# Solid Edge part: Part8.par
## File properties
Author: Deepak Maini
Template: Normal.par
Last saved by: MYPC
Revision: 38
Application: Solid Edge
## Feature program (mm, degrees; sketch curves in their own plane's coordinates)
sketch for "unnamed Protrusion 1" plane through (0, 0, 0) normal (0, 0, 1) x-axis (1, 0, 0)
  arc centre (32.4919, 0.608) radius 66.4976 from (-33.994, -0.6361) to (-18.3494, 43.4693) cw
  arc centre (0, 28) radius 24 from (-18.3494, 43.4693) to (18.3494, 43.4693) cw
  arc centre (-32.4919, 0.608) radius 66.4976 from (18.3494, 43.4693) to (33.994, -0.6361) cw
  arc centre (0, 0) radius 34 from (33.994, -0.6361) to (-33.994, -0.6361) cw
extrude "unnamed Protrusion 1" add finite 6 along -normal
sketch for "unnamed RevolvedProtrusion 1" plane through (0, 0, 0) normal (0, 0, 1) x-axis (1, 0, 0)
  line (0, 52) -> (0, -34)
  arc centre (0, 0) radius 34 from (0, -34) to (-33.994, -0.6361) cw
  arc centre (32.4919, 0.608) radius 66.4976 from (-33.994, -0.6361) to (-18.3494, 43.4693) cw
  arc centre (0, 28) radius 24 from (-18.3494, 43.4693) to (0, 52) cw
revolve "unnamed RevolvedProtrusion 1" add finite about sketch line (0, 51.9687) -> (0, 65.9821)
fillet "unnamed Round 1"
sketch for "unnamed Cutout 1" #1 plane through (0, 4, -6) normal (0, 0, -1) x-axis (-1, 0, 0)
  circle centre (13, -19) radius 2.5
sketch for "unnamed Cutout 1" #2 plane through (0, 4, -6) normal (0, 0, -1) x-axis (-1, 0, 0)
  circle centre (-13, -19) radius 2.5
  dimension (linear) = 13
extrude "unnamed Cutout 1" cut finite 3 along -normal
thinwall "unnamed Thinwall 1"
sketch for "unnamed Cutout 2" plane through (0, 0, 0) normal (0, 0, 1) x-axis (1, 0, 0)
  circle centre (0, 11) radius 8
extrude "unnamed Cutout 2" cut through along -normal
chamfer "unnamed Chamfer 1"
sketch for "unnamed Cutout 3" plane through (0, 0, 0) normal (0, -1, 0) x-axis (1, 0, 0)
  circle centre (0, 0) radius 3
extrude "unnamed Cutout 3" cut through along -normal
sketch for "unnamed Protrusion 2" plane through (0, 0, 1) normal (0, 0, 1) x-axis (1, 0, 0)
  circle centre (-13, -15) radius 2.5
extrude "unnamed Protrusion 2" add through along +normal
mirror "unnamed Mirror 1" of "unnamed Protrusion 2" about plane through (0, 0, 0) normal (1, 0, 0)
extrude "unnamed Protrusion 3" add through
web network "unnamed WebNetwork 1"
rib "unnamed Rib 1"
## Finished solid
Body 1: sheet body, 1 face, 4 edges, 4 vertices.
  Faces by surface: plane 1
  Edges by curve: line 4
Body 2: sheet body, 1 face, 2 edges, 0 vertices.
  Faces by surface: cylinder 1
  Edges by curve: circle 2
Body 3: sheet body, 1 face, 3 edges, 2 vertices.
  Faces by surface: swept 1
  Edges by curve: ellipse 2, line 1
Body 4: solid body, 67 faces, 159 edges, 96 vertices.
  Faces by surface: plane 39, cylinder 13, torus 10, sphere 4, cone 1
  Edges by curve: circle 71, line 67, intersection 21
Bounding box of the edges (mm; curved faces can reach further): 139.700 x 105.279 x 54.293, from (-69.85, -45.1917, -6) to (69.85, 60.0873, 48.2926).
Cylindrical faces by radius (mm): R2.5 x6, R3 x1, R4.5 x2, R8 x1, R10.5 x1, R12.5 x2, R14 x1
Conical faces (half-angle, radius in mm at the cone's reference point): 45 deg R8 x1
Toroidal faces (ring radius, tube radius in mm): R-32.4919 r64.4976 x1, R-32.4919 r66.4976 x1, R18 r4 x1, R18 r6 x1, R28 r4 x1, R28 r6 x1, R60.4976 r4 x2, R60.4976 r6 x2
Spherical faces by radius (mm): R22 x1, R24 x1, R32 x1, R34 x1
Planar faces by outward normal: +x 5, +y 7, +z 10, -x 4, -y 8, -z 5
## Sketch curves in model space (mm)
arc centre (-28, -15, 1) radius 12.5 from (-15.5, -15, 1) through (-17.1245, -15, 7.1623) to (-21.5758, -15, 11.7228)
line (-10.5, -15, 1) -> (-15.5, -15, 1)
arc centre (0, -15, 1) radius 10.5 from (10.5, -15, 1) through (-0.3111, -15, 11.4954) to (-10.5, -15, 1)
line (15.5, -15, 1) -> (10.5, -15, 1)
arc centre (28, -15, 1) radius 12.5 from (21.5758, -15, 11.7228) through (17.1245, -15, 7.1623) to (15.5, -15, 1)
line (0, -0.5987, 0) -> (0, -32, 0)
line (0, 49.7945, 0) -> (0, 42.1802, 0)
line (0, 42.1802, 0) -> (0, -0.5987, 0)
line (0, -34, 0) -> (0, -45.1917, 0)
line (0, -0.6361, 0) -> (0, -34, 0)
line (0, 51.8118, 0) -> (0, 60.0873, 0)
line (0, 43.4693, 0) -> (0, 51.8118, 0)
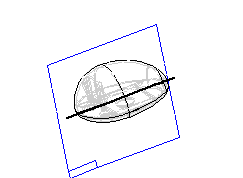
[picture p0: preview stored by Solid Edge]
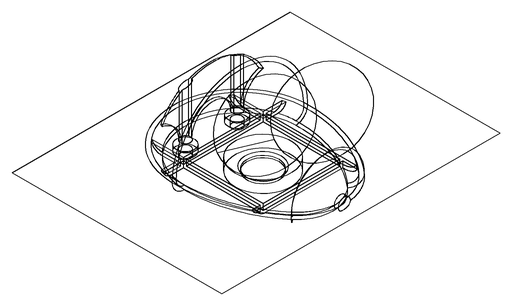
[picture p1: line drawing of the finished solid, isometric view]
